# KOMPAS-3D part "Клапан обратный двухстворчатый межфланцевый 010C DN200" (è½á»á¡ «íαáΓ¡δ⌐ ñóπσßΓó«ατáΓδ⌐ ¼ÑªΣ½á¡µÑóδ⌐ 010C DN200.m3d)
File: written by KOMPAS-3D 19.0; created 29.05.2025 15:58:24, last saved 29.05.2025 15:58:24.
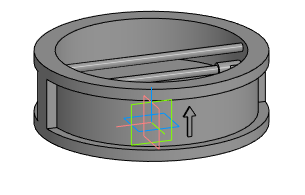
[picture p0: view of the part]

Document properties: Полное имя файла: E:\Dendor Работа Сачек\3D для проекитирвщиков\5.2 Тип 010C, 010C.Y Клапан обратный двухстворчатый межфланцевый\stp_Клапан обратный двухстворчатый межфланцевый 010C\Клапан обратный двухстворчатый межфланцевый 010C DN200.m3d

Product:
- Part/product: Клапан обратный двухстворчатый межфланцевый 010C DN200

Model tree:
1. Операция без истории:1  (labels: Клапан обратный двухстворчатый межфланцевый 010C DN200)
